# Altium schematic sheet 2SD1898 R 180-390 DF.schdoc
size 127 x 101 mm
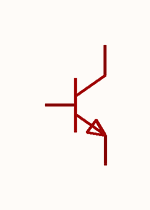
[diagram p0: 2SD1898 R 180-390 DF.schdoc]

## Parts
Q?  2sd1898(range:180-390)  [SOT-89-3_L4.5-W2.5-P1.50-LS4.2-BR]  (value not drawn)

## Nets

Not connected (* = marked no-connect by the designer): Q? 1 2 3

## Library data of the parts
Q? = 2sd1898(range:180-390): 晶体管类型:NPN;集电极电流(Ic):1A;集射极击穿电压(Vceo):80V;耗散功率(Pd):500mW;直流电流增益(hFE):180;; Manufacturer: CJ(江苏长电/长晶); Symbol: 2SD1898 R 180-390 DF; AddInBom: yes; ModelId: 6db690b7897d4d18a30d90c1b89525ee; ModelName: SOT-89-3_L4.3-W2.5-H1.6-LS4.1-P1.50; ModelTransform: 161.417,169.291,0,180,0,0,-18.661,0,0; type: NPN; Current - Collector(Ic): 1A; Collector - Emitter Voltage VCEO: 80V; Pd - Power Dissipation: 500mW; DC Current Gain: 180; Transition frequency(fT): 100MHz; Current - Collector Cutoff: 1uA; Vce Saturation(VCE(sat)): 400mV; Emitter-Base Voltage(Vebo): 5V; Number: 1个NPN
